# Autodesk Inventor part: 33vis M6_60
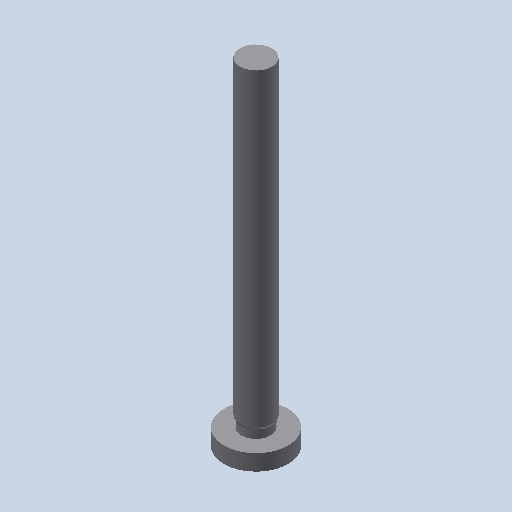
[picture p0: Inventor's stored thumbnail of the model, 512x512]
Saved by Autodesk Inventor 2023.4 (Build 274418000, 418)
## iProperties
Created: 2011-01
Part Number: 33vis M6_60
Document SubType Name: Modeling
Designer: eric
Density: 1 g/cm^3
Mass: 2.06284 g
Surface Area: 15.3346 cm^2
Volume: 2.06284 cm^3
Material: Générique
Appearance: Par défaut
Author: eric
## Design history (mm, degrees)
feature "Base1"
node "Corps solides"
node "Corps surfaciques"
node "Solide1"
